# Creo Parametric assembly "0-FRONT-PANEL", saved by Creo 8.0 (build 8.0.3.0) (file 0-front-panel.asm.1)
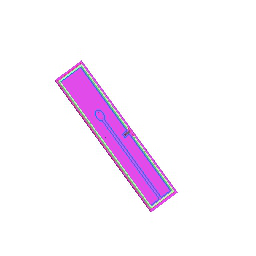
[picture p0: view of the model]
Units: millimeter Newton Second (mmNs); MM, TONNE, SECS

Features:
  1. datum plane "ADTM1"
  2. datum plane "ADTM2"
  3. datum plane "ADTM3"
  4. coordinate system
  5. component "1_FRONT-PANEL"
  6. component "1_REINFORCE1_FRONT-PANEL"
  7. component "1_REINFORCE2_FRONT-PANEL"
  8. component "1_REINFORCE4_FRONT-PANEL"
  9. component "1_REINFORCE3_FRONT-PANEL"
  10. component "1_REINFORCE5_FRONT-PANEL"
  11. component "4_DELL_LOGO"
  12. component "1_DOOR-SPINDLE"
  13. component "1_DOOR-SPINDLE"
  14. component "4_LOCK"
  15. component "SPONGE-PAD"

Other named items: COPIED_GROUP, ACS0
